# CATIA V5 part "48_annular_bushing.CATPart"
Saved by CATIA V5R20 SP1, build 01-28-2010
Part number: 48_annular_bushing
Bounding box of the stored display mesh (mm): x -29.242 to 29.242, y 111.129 to 169.594, z -153.5 to -118.5
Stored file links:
  C:\Documents and Settings\anizard\Bureau\13\48_annular_bushing.CATPart
  C:\Documents and Settings\anizard\Bureau\13\anizard.CATProduct
  C:\Documents and Settings\anizard\Bureau\13\16_C-shaped_bracket.CATPart
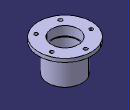
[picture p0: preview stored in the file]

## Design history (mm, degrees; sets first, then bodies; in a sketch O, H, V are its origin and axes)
Set1
  Line1: linked copy from another document
  Point1 to Point4: linked copy from another document
  Plane1 to Plane5: linked copy from another document
  Line2: linked copy from another document
Body1 (main body)
  Sketch1 on yz-plane, origin (0, 0, 0), H (0, 1, 0), V (0, 0, 1)
    line L1 (154.3619, -143.5) -> (154.3619, -128.5)
    line L2 (154.3619, -128.5) -> (155.3619, -128.5)
    line L3 (155.3619, -128.5) -> (155.3619, -118.5)
    line L4 (155.3619, -118.5) -> (169.6119, -118.5)
    line L5 (169.6119, -118.5) -> (169.6119, -122.5)
    line L6 (169.6119, -122.5) -> (159.3619, -122.5)
    line L7 (159.3619, -122.5) -> (159.3619, -153.5)
    line L8 (159.3619, -153.5) -> (155.3619, -153.5)
    point P9 (155.3619, -153.5)
    line L9 (155.3619, -153.5) -> (155.3619, -143.5)
    line L10 (155.3619, -143.5) -> (154.3619, -143.5)
    reference projected point E1 (155.3619, -122.5) from Point1
    reference projected point E2 (159.3619, -122.5) from Point2
    reference projected point E3 (169.6119, -122.5) from Point3
    reference intersected line E4 through (0, -118.5) direction (-1, 0) from Plane1
    reference intersected line E5 through (0, -122.5) direction (-1, 0) from Plane2
    reference intersected line E6 through (0, -128.5) direction (-1, 0) from Plane3
    reference intersected line E7 through (0, -143.5) direction (-1, 0) from Plane4
    reference intersected line E8 through (0, -153.5) direction (-1, 0) from Plane5
    distance L3 L1 = 1
    vertical: L1 V, L3 V, L5 V, L7 V, L9 V
    horizontal: L2 H, L4 H, L6 H, L8 H, L10 H
    coincidence: P9 L3, L3 E1, L7 E2, L5 E3, L4 E4, L6 E5, L2 E6, L10 E7, E8 L8
  Shaft1: profile Sketch1, axis Line2, angle 360
  Sketch2 on face of Shaft1 from Sketch1.L4, origin (0, 169.6119, -118.5), H (1, 0, 0), V (0, 1, 0)
    point P1 (0, -6.25)
    reference projected point E1 (0, -6.25) from Point4
    coincidence: E1 P1
  Hole1: placed by Sketch2, at (0, 163.3619, -118.5) direction (0, 0, -1), diameter 4, up to Plane2
  CircPattern1: of Hole1, instances 6, angular step 72, axis from Line2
